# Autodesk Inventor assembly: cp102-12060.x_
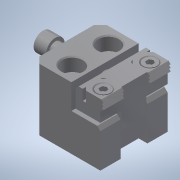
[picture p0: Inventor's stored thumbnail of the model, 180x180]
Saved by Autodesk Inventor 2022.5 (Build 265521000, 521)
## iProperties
Part Number: cp102-12060.x_
Material: 一般
Document SubType Name: Assembly
Designer: ImaoCorp
Sending System: SOLIDWORKS 2017-2017317
MC: AMD64
MC_MODEL: Intel64 Family 6 Model 60 Stepping 3, GenuineIntel
OS: Windows_NT
FRU: Parasolid Version 29.0, build 201,  4-17-2017
FORMAT: text
GUISE: transmit
KEY: cp102-12060
FILE: cp102-12060.x_t
DATE: Thu Apr 04 16:34:51 2019
Author: ImaoCorp
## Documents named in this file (3)
- X:\14_SW2022-Inv2022\00_全2023-1023新製品(TCC)まで\c\cp102-12060\CP102-12060.iam
- X:\14_SW2022-Inv2022\00_全2023-1023新製品(TCC)まで\c\cp102-12060\cp102-12060_01.ipt
- X:\14_SW2022-Inv2022\00_全2023-1023新製品(TCC)まで\c\cp102-12060\cp102-12060_02.ipt
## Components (2 placed, 2 different names)
1. cp102-12060_01
2. cp102-12060_02
